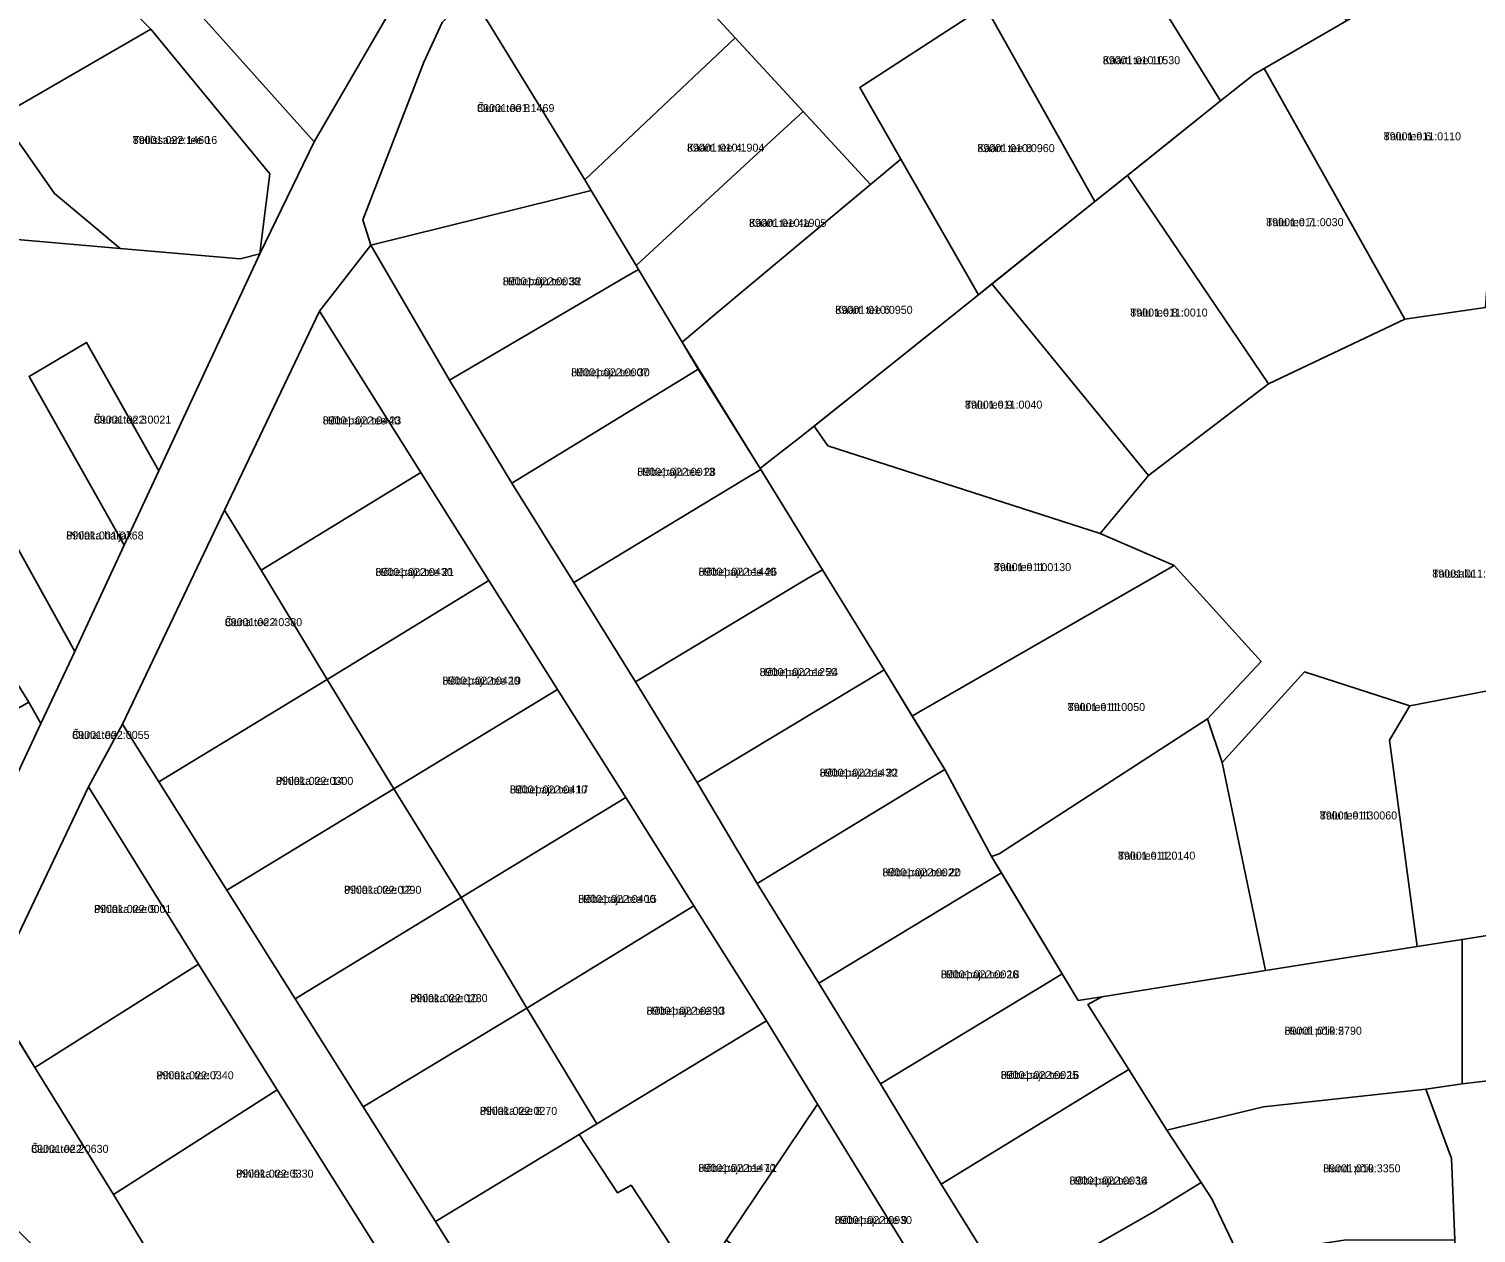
# Model space of a CAD drawing. Extents: x 526849 to 562296, y 6591741 to 6618546.
# Drawn here: x 546108.1 to 546379.4, y 6598045.1 to 6598270.9 of the extents above; entities that cross this region are included whole.
import ezdxf

# ---------------------------------------------------------------- set-up
doc = ezdxf.new("R2010")
doc.units = 0
for name, color, linetype in [('L_AADRESS', 7, 'Continuous'), ('PIIR', 7, 'Continuous'), ('TUNNUS', 7, 'Continuous')]:
    doc.layers.add(name, color=color, linetype=linetype)

msp = doc.modelspace()

# ---------------------------------------------------------------- linework, layer by layer
at = {"layer": 'PIIR'}
for points in [[(546206.41, 6598306.21), (546214.11, 6598319.98), (546216.46, 6598317.41), (546241.19, 6598289.86), (546255.93, 6598320.34), (546257.43, 6598323.43), (546266.79, 6598308.31), (546252.36, 6598278.5), (546257.11, 6598273.35), (546279.71, 6598287.47), (546287.35, 6598275.14), (546263.87, 6598259.89), (546271.56, 6598246.44), (546265.88, 6598241.7), (546240.54, 6598269.19), (546209.4, 6598302.97)], [(546212.34, 6598242.59), (546194.26, 6598272), (546190.8, 6598277.39), (546194.5, 6598284.94), (546206.41, 6598306.21), (546209.4, 6598302.97), (546240.54, 6598269.19), (546218.15, 6598248.07)], [(546311.3, 6598289.99), (546335.1, 6598304.74), (546355.13, 6598272.42), (546339.68, 6598263.49), (546337.75, 6598262.37), (546331.51, 6598257.38)], [(546138.09, 6598275.97), (546166.15, 6598300.42), (546181.28, 6598283.63), (546161.61, 6598249.69)], [(546081.89, 6598287.45), (546083.01, 6598289.85), (546109.46, 6598287.9), (546120.25, 6598281.53), (546130.98, 6598270.84), (546102.79, 6598254.56)], [(546287.35, 6598275.14), (546311.3, 6598289.99), (546331.51, 6598257.38), (546307.96, 6598238.54)], [(546381.17, 6598218.64), (546366.08, 6598216.45), (546339.68, 6598263.49), (546355.13, 6598272.42), (546379.38, 6598286.44), (546384.05, 6598289.14), (546384.48, 6598271.96), (546381.59, 6598224.76)], [(546110.37, 6598140.63), (546108.1, 6598144.68), (546095.94, 6598164.16), (546084.55, 6598185.41), (546073.57, 6598205.99), (546066.7, 6598218.63), (546055.84, 6598237.71), (546049.19, 6598249.4), (546046.4, 6598254.43), (546039.19, 6598267.46), (546028.8, 6598286.32), (546042.81, 6598288.02), (546052.12, 6598270.62), (546075.45, 6598228.58), (546078.83, 6598222.48), (546116.7, 6598154.14)], [(546042.81, 6598288.02), (546081.89, 6598287.45), (546102.79, 6598254.56), (546112.94, 6598240.06), (546118.96, 6598234.99), (546125.21, 6598229.73), (546103.72, 6598231.57), (546078.83, 6598222.48), (546075.45, 6598228.58), (546052.12, 6598270.62)], [(546207.29, 6598239.04), (546172.21, 6598230.37), (546170.73, 6598235.08), (546182.13, 6598264.66), (546185.6, 6598272.1), (546190.8, 6598277.39), (546194.26, 6598272), (546212.34, 6598242.59), (546213.54, 6598240.59)], [(546286.1, 6598221.04), (546271.56, 6598246.44), (546263.87, 6598259.89), (546287.35, 6598275.14), (546307.96, 6598238.54)], [(546130.98, 6598270.84), (546153.28, 6598243.74), (546151.87, 6598232.37), (546151.42, 6598228.69), (546147.74, 6598227.79), (546125.21, 6598229.73), (546118.96, 6598234.99), (546112.94, 6598240.06), (546102.79, 6598254.56)], [(546212.34, 6598242.59), (546218.15, 6598248.07), (546240.54, 6598269.19), (546253.25, 6598255.4), (546248.05, 6598250.66), (546237.38, 6598240.78), (546224.47, 6598228.86), (546221.96, 6598226.54), (546213.54, 6598240.59)], [(546331.51, 6598257.38), (546337.75, 6598262.37), (546339.68, 6598263.49), (546366.08, 6598216.45), (546340.51, 6598204.33), (546314.04, 6598243.39)], [(546221.96, 6598226.54), (546224.47, 6598228.86), (546237.38, 6598240.78), (546248.05, 6598250.66), (546253.25, 6598255.4), (546265.88, 6598241.7), (546237.48, 6598217.94), (546230.58, 6598212.16), (546222.4, 6598225.81)], [(546246.5, 6598189.52), (546245.18, 6598188.5), (546230.58, 6598212.16), (546237.48, 6598217.94), (546265.88, 6598241.7), (546271.56, 6598246.44), (546286.1, 6598221.04), (546252.66, 6598194.28)], [(546288.65, 6598223.08), (546307.96, 6598238.54), (546314.04, 6598243.39), (546340.51, 6598204.33), (546318, 6598187.14)], [(546172.21, 6598230.37), (546207.29, 6598239.04), (546213.54, 6598240.59), (546221.96, 6598226.54), (546222.4, 6598225.81), (546219.76, 6598224.26), (546186.95, 6598205.05)], [(546116.7, 6598154.14), (546078.83, 6598222.48), (546103.72, 6598231.57), (546125.21, 6598229.73), (546147.74, 6598227.79), (546151.42, 6598228.69), (546132.46, 6598188.03), (546118.9, 6598212.11), (546108.15, 6598205.72), (546125.97, 6598174.09)], [(546186.95, 6598205.05), (546219.76, 6598224.26), (546222.4, 6598225.81), (546230.58, 6598212.16), (546233.6, 6598207.1), (546231.27, 6598205.68), (546198.65, 6598185.69)], [(546286.1, 6598221.04), (546288.65, 6598223.08), (546318, 6598187.14), (546308.93, 6598176.3), (546257.9, 6598192.72), (546255.32, 6598196.4)], [(546181.6, 6598187.75), (546151.65, 6598169.41), (546144.78, 6598180.66), (546162.57, 6598217.96)], [(546108.15, 6598205.72), (546118.9, 6598212.11), (546132.46, 6598188.03), (546125.97, 6598174.09)], [(546198.65, 6598185.69), (546231.27, 6598205.68), (546233.6, 6598207.1), (546245.18, 6598188.5), (546245.32, 6598188.27), (546242.08, 6598186.32), (546210.26, 6598167.1)], [(546273.69, 6598142.06), (546268.43, 6598150.69), (546256.86, 6598169.5), (546245.18, 6598188.5), (546246.5, 6598189.52), (546252.66, 6598194.28), (546255.32, 6598196.4), (546257.9, 6598192.72), (546308.93, 6598176.3), (546322.78, 6598170.27), (546274.96, 6598142.8)], [(546151.65, 6598169.41), (546181.6, 6598187.75), (546194.35, 6598167.5), (546164.02, 6598148.89)], [(546210.26, 6598167.1), (546242.08, 6598186.32), (546245.32, 6598188.27), (546256.86, 6598169.5), (546253.98, 6598167.77), (546221.82, 6598148.45)], [(546125.66, 6598140.54), (546144.78, 6598180.66), (546151.65, 6598169.41), (546164.02, 6598148.89), (546132.45, 6598129.75)], [(546288.59, 6598115.72), (546279.79, 6598132.05), (546273.69, 6598142.06), (546274.96, 6598142.8), (546322.78, 6598170.27), (546339.09, 6598152.31), (546329.04, 6598141.53), (546290.02, 6598116.24)], [(546164.02, 6598148.89), (546194.35, 6598167.5), (546207.22, 6598147.05), (546176.5, 6598128.39)], [(546221.82, 6598148.45), (546253.98, 6598167.77), (546256.86, 6598169.5), (546268.43, 6598150.69), (546265.68, 6598149.04), (546233.37, 6598129.61)], [(546279.79, 6598132.05), (546276.98, 6598130.34), (546244.66, 6598110.68), (546233.37, 6598129.61), (546265.68, 6598149.04), (546268.43, 6598150.69)], [(546132.45, 6598129.75), (546164.02, 6598148.89), (546176.5, 6598128.39), (546145.24, 6598109.41)], [(546331.82, 6598133.34), (546347.23, 6598150.32), (546366.96, 6598143.94), (546363.17, 6598137.55), (546368.39, 6598098.86), (546339.93, 6598094.32)], [(546368.39, 6598098.86), (546363.17, 6598137.55), (546366.96, 6598143.94), (546397.1, 6598149.76), (546393.9, 6598143.04), (546398.66, 6598103.68), (546376.79, 6598100.19)], [(546176.5, 6598128.39), (546207.22, 6598147.05), (546220, 6598126.77), (546189.14, 6598108.02)], [(546069.25, 6598122.33), (546108.1, 6598144.68), (546110.37, 6598140.63), (546087.53, 6598091.82), (546080.56, 6598103.31)], [(546138.76, 6597966.31), (546127.94, 6597973.3), (546137.78, 6597988.59), (546150.73, 6598008.66), (546172.92, 6598043), (546154.68, 6598072), (546139.88, 6598095.54), (546119.28, 6598128.76), (546125.66, 6598140.54), (546132.45, 6598129.75), (546145.24, 6598109.41), (546158.03, 6598089.06), (546170.77, 6598068.81), (546184.31, 6598047.28), (546188.27, 6598040.98), (546183.43, 6598033.78), (546171.67, 6598016.31), (546160.66, 6597999.6)], [(546306.8, 6598089.05), (546304.83, 6598088.74), (546288.59, 6598115.72), (546290.02, 6598116.24), (546329.04, 6598141.53), (546331.82, 6598133.34), (546339.93, 6598094.32), (546309.26, 6598089.44)], [(546244.66, 6598110.68), (546276.98, 6598130.34), (546279.79, 6598132.05), (546288.59, 6598115.72), (546290.44, 6598112.64), (546288.26, 6598111.32), (546256.18, 6598091.96)], [(546139.88, 6598095.54), (546109.21, 6598076.15), (546100.78, 6598090), (546119.28, 6598128.76)], [(546145.24, 6598109.41), (546176.5, 6598128.39), (546189.14, 6598108.02), (546158.03, 6598089.06)], [(546189.14, 6598108.02), (546220, 6598126.77), (546232.78, 6598106.48), (546201.44, 6598087.27)], [(546256.18, 6598091.96), (546288.26, 6598111.32), (546290.44, 6598112.64), (546301.83, 6598093.71), (546299.7, 6598092.42), (546267.73, 6598073.12)], [(546158.03, 6598089.06), (546189.14, 6598108.02), (546201.44, 6598087.27), (546170.77, 6598068.81)], [(546201.44, 6598087.27), (546232.78, 6598106.48), (546246.38, 6598084.88), (546214.58, 6598065.62)], [(546414.68, 6598054.98), (546382.73, 6598059.18), (546383.18, 6598073.88), (546376.79, 6598073.08), (546376.79, 6598100.19), (546398.66, 6598103.68), (546412.78, 6598105.93), (546416.72, 6598067.81)], [(546323.74, 6598064.98), (546321.41, 6598064.42), (546314.3, 6598075.79), (546306.65, 6598087.96), (546309.26, 6598089.44), (546339.93, 6598094.32), (546368.39, 6598098.86), (546376.79, 6598100.19), (546376.79, 6598073.08), (546370, 6598072.12), (546339.58, 6598068.76)], [(546139.88, 6598095.54), (546154.68, 6598072), (546123.97, 6598052.36), (546109.21, 6598076.15)], [(546267.73, 6598073.12), (546299.7, 6598092.42), (546301.83, 6598093.71), (546304.83, 6598088.74), (546306.8, 6598089.05), (546309.26, 6598089.44), (546306.65, 6598087.96), (546314.3, 6598075.79), (546311.09, 6598073.83), (546279.14, 6598054.31)], [(546100.13, 6598090.84), (546109.21, 6598076.15), (546123.97, 6598052.36), (546132.03, 6598039.02), (546122.27, 6598029.23), (546105.99, 6598045.66), (546099.1, 6598046.55), (546085.05, 6598060.2)], [(546170.77, 6598068.81), (546201.44, 6598087.27), (546214.58, 6598065.62), (546211.25, 6598063.6), (546184.31, 6598047.28)], [(546238.84, 6598043.79), (546233.26, 6598035.49), (546221.01, 6598054.07), (546218.45, 6598052.69), (546211.25, 6598063.6), (546214.58, 6598065.62), (546246.38, 6598084.88), (546255.97, 6598069.28)], [(546279.14, 6598054.31), (546311.09, 6598073.83), (546314.3, 6598075.79), (546321.41, 6598064.42), (546327.85, 6598054.63), (546324.6, 6598052.61), (546319.08, 6598049.19), (546301.13, 6598038.92), (546296.14, 6598035.48), (546291.6, 6598032.65), (546291.71, 6598034.02)], [(546334.92, 6598040.9), (546329.9, 6598051.52), (546321.41, 6598064.42), (546323.74, 6598064.98), (546339.58, 6598068.76), (546370, 6598072.12), (546374.77, 6598059.12), (546375.4, 6598043.88), (546354.65, 6598043.77), (546337.33, 6598041.14)], [(546123.97, 6598052.36), (546154.68, 6598072), (546172.92, 6598043), (546132.03, 6598039.02)], [(546272.24, 6598020.32), (546238.84, 6598043.79), (546255.97, 6598069.28), (546279.47, 6598031.12)], [(546183.43, 6598033.78), (546188.27, 6598040.98), (546184.31, 6598047.28), (546211.25, 6598063.6), (546218.45, 6598052.69), (546221.01, 6598054.07), (546233.26, 6598035.49), (546227.76, 6598027.31), (546217.25, 6598010.08)], [(546291.6, 6598032.65), (546296.14, 6598035.48), (546301.13, 6598038.92), (546319.08, 6598049.19), (546324.6, 6598052.61), (546327.85, 6598054.63), (546329.9, 6598051.52), (546334.92, 6598040.9), (546338.94, 6598030.72), (546335.75, 6598029.12), (546315.84, 6598018.56), (546303.43, 6598012.12), (546294.56, 6598026.07), (546291.42, 6598030.94)]]:
    msp.add_lwpolyline(points, close=True, dxfattribs=at)
for points in [[(546087.53, 6598091.82), (546110.37, 6598140.63), (546116.7, 6598154.14), (546125.97, 6598174.09), (546132.46, 6598188.03), (546151.42, 6598228.69), (546161.61, 6598249.69), (546181.28, 6598283.63)], [(546138.09, 6598275.97), (546161.61, 6598249.69), (546151.42, 6598228.69), (546151.87, 6598232.37), (546153.28, 6598243.74), (546130.98, 6598270.84), (546120.25, 6598281.53)], [(546185.6, 6598272.1), (546182.13, 6598264.66), (546170.73, 6598235.08), (546172.21, 6598230.37), (546162.57, 6598217.96), (546144.78, 6598180.66), (546125.66, 6598140.54), (546119.28, 6598128.76), (546100.78, 6598090)], [(546279.47, 6598031.12), (546255.97, 6598069.28), (546246.38, 6598084.88), (546232.78, 6598106.48), (546220, 6598126.77), (546207.22, 6598147.05), (546194.35, 6598167.5), (546181.6, 6598187.75), (546162.57, 6598217.96), (546172.21, 6598230.37), (546186.95, 6598205.05), (546198.65, 6598185.69), (546210.26, 6598167.1), (546221.82, 6598148.45), (546233.37, 6598129.61), (546244.66, 6598110.68), (546256.18, 6598091.96), (546267.73, 6598073.12), (546279.14, 6598054.31), (546291.71, 6598034.02)], [(546397.1, 6598149.76), (546366.96, 6598143.94), (546347.23, 6598150.32), (546331.82, 6598133.34), (546329.04, 6598141.53), (546339.09, 6598152.31), (546322.78, 6598170.27), (546308.93, 6598176.3), (546318, 6598187.14), (546340.51, 6598204.33), (546366.08, 6598216.45), (546381.17, 6598218.64)], [(546260.77, 6597910.82), (546273.57, 6597929.92), (546286.4, 6597949.07), (546299.52, 6597967.59), (546305.15, 6597971.17), (546310.49, 6597974.03), (546329.99, 6597984.39), (546348.6, 6597994.03), (546352.6, 6597996.63), (546354.99, 6597997.38), (546376.95, 6598004.29), (546375.4, 6598043.88), (546374.77, 6598059.12), (546370, 6598072.12), (546376.79, 6598073.08), (546383.18, 6598073.88)]]:
    msp.add_lwpolyline(points, dxfattribs=at)

# ---------------------------------------------------------------- texts
at = {"layer": 'L_AADRESS'}
for s, p in [('Käärti tee 10', (546309.43, 6598264.27)), ('Õuna tee 8', (546192.13, 6598255.3)), ('Talu tee 6', (546362.08, 6598250.01)), ('Tellissaare tee 16', (546127.58, 6598249.32)), ('Käärti tee 4', (546231.48, 6598247.87)), ('Käärti tee 8', (546285.91, 6598247.79)), ('Käärti tee 4a', (546243.11, 6598233.78)), ('Talu tee 7', (546340.06, 6598233.9)), ('Hõbepaju tee 32', (546196.95, 6598222.82)), ('Käärti tee 6', (546259.28, 6598217.47)), ('Talu tee 8', (546314.58, 6598216.96)), ('Hõbepaju tee 30', (546209.77, 6598205.75)), ('Talu tee 9', (546283.59, 6598199.69)), ('Õuna tee 3', (546120.3, 6598196.88)), ('Hõbepaju tee 23', (546163.19, 6598196.73)), ('Hõbepaju tee 28', (546222.16, 6598187.1)), ('Pihlaka haljak', (546115.12, 6598175.16)), ('Hõbepaju tee 21', (546173.07, 6598168.32)), ('Hõbepaju tee 26', (546233.65, 6598168.36)), ('Talu tee 10', (546289, 6598169.23)), ('Talusalu', (546371.2, 6598168.02)), ('Õuna tee 4', (546144.84, 6598158.91)), ('Hõbepaju tee 24', (546245.1, 6598149.55)), ('Hõbepaju tee 19', (546185.63, 6598147.95)), ('Talu tee 11', (546302.85, 6598142.99)), ('Õuna tee', (546116.24, 6598137.77)), ('Hõbepaju tee 22', (546256.35, 6598130.69)), ('Pihlaka tee 14', (546154.43, 6598129.15)), ('Hõbepaju tee 17', (546198.27, 6598127.54)), ('Talu tee 13', (546350.11, 6598122.67)), ('Talu tee 12', (546312.27, 6598115.13)), ('Hõbepaju tee 20', (546268.11, 6598112.01)), ('Pihlaka tee 12', (546167.19, 6598108.73)), ('Hõbepaju tee 15', (546211.09, 6598107.02)), ('Pihlaka tee 9', (546120.33, 6598105.12)), ('Hõbepaju tee 18', (546279.08, 6598092.88)), ('Pihlaka tee 10', (546179.6, 6598088.41)), ('Hõbepaju tee 13', (546223.91, 6598086.05)), ('Hundi põik 5', (546343.5, 6598082.31)), ('Pihlaka tee 7', (546132.01, 6598073.95)), ('Hõbepaju tee 16', (546290.29, 6598074.01)), ('Pihlaka tee 8', (546192.66, 6598067.28)), ('Õuna tee 2', (546108.54, 6598060.16)), ('Pihlaka tee 5', (546146.97, 6598055.51)), ('Hõbepaju tee 11', (546233.61, 6598056.58)), ('Hõbepaju tee 14', (546303.19, 6598054.22)), ('Hundi põik 3', (546350.75, 6598056.51)), ('Hõbepaju tee 9', (546259.16, 6598046.81))]:
    msp.add_text(s, height=1.5, dxfattribs=at).set_placement(p)
at = {"layer": 'TUNNUS'}
for s, p in [('89001:010:1530', (546309.43, 6598264.27)), ('89001:001:1469', (546192.13, 6598255.3)), ('89001:011:0110', (546362.08, 6598250.01)), ('89001:022:1460', (546127.58, 6598249.32)), ('89001:010:1904', (546231.48, 6598247.87)), ('89001:010:0960', (546285.91, 6598247.79)), ('89001:010:1905', (546243.11, 6598233.78)), ('89001:011:0030', (546340.06, 6598233.9)), ('89001:022:0038', (546196.95, 6598222.82)), ('89001:010:0950', (546259.28, 6598217.47)), ('89001:011:0010', (546314.58, 6598216.96)), ('89001:022:0007', (546209.77, 6598205.75)), ('89001:011:0040', (546283.59, 6598199.69)), ('89001:022:0021', (546120.3, 6598196.88)), ('89001:022:0440', (546163.19, 6598196.73)), ('89001:022:0013', (546222.16, 6598187.1)), ('89001:001:0768', (546115.12, 6598175.16)), ('89001:022:0430', (546173.07, 6598168.32)), ('89001:022:1440', (546233.65, 6598168.36)), ('89001:011:0130', (546289, 6598169.23)), ('89001:011:0170', (546371.2, 6598168.02)), ('89001:022:0380', (546144.84, 6598158.91)), ('89001:022:1250', (546245.1, 6598149.55)), ('89001:022:0420', (546185.63, 6598147.95)), ('89001:011:0050', (546302.85, 6598142.99)), ('89001:022:0055', (546116.24, 6598137.77)), ('89001:022:1430', (546256.35, 6598130.69)), ('89001:022:0300', (546154.43, 6598129.15)), ('89001:022:0410', (546198.27, 6598127.54)), ('89001:011:0060', (546350.11, 6598122.67)), ('89001:011:0140', (546312.27, 6598115.13)), ('89001:022:0022', (546268.11, 6598112.01)), ('89001:022:0290', (546167.19, 6598108.73)), ('89001:022:0400', (546211.09, 6598107.02)), ('89001:022:0001', (546120.33, 6598105.12)), ('89001:022:0026', (546279.08, 6598092.88)), ('89001:022:0280', (546179.6, 6598088.41)), ('89001:022:0390', (546223.91, 6598086.05)), ('89001:010:2790', (546343.5, 6598082.31)), ('89001:022:0340', (546132.01, 6598073.95)), ('89001:022:0025', (546290.29, 6598074.01)), ('89001:022:0270', (546192.66, 6598067.28)), ('89001:022:0630', (546108.54, 6598060.16)), ('89001:022:0330', (546146.97, 6598055.51)), ('89001:022:1470', (546233.61, 6598056.58)), ('89001:022:0036', (546303.19, 6598054.22)), ('89001:010:3350', (546350.75, 6598056.51)), ('89001:022:0930', (546259.16, 6598046.81))]:
    msp.add_text(s, height=1.5, dxfattribs=at).set_placement(p)

doc.saveas('drawing.dxf')
